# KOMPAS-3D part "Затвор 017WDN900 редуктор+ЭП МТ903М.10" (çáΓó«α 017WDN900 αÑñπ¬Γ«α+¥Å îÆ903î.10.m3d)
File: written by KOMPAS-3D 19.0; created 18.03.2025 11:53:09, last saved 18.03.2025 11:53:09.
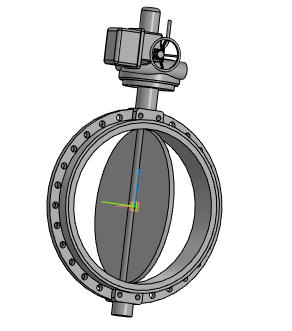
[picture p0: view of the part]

Document properties: Автор: Евгений; Полное имя файла: Затвор 017WDN900 редуктор+ЭП МТ903М.10.a3d

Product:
- Part/product: Затвор 017WDN900 редуктор+ЭП МТ903М.10
    Масса: 710.621

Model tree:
1. Операция без истории:1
